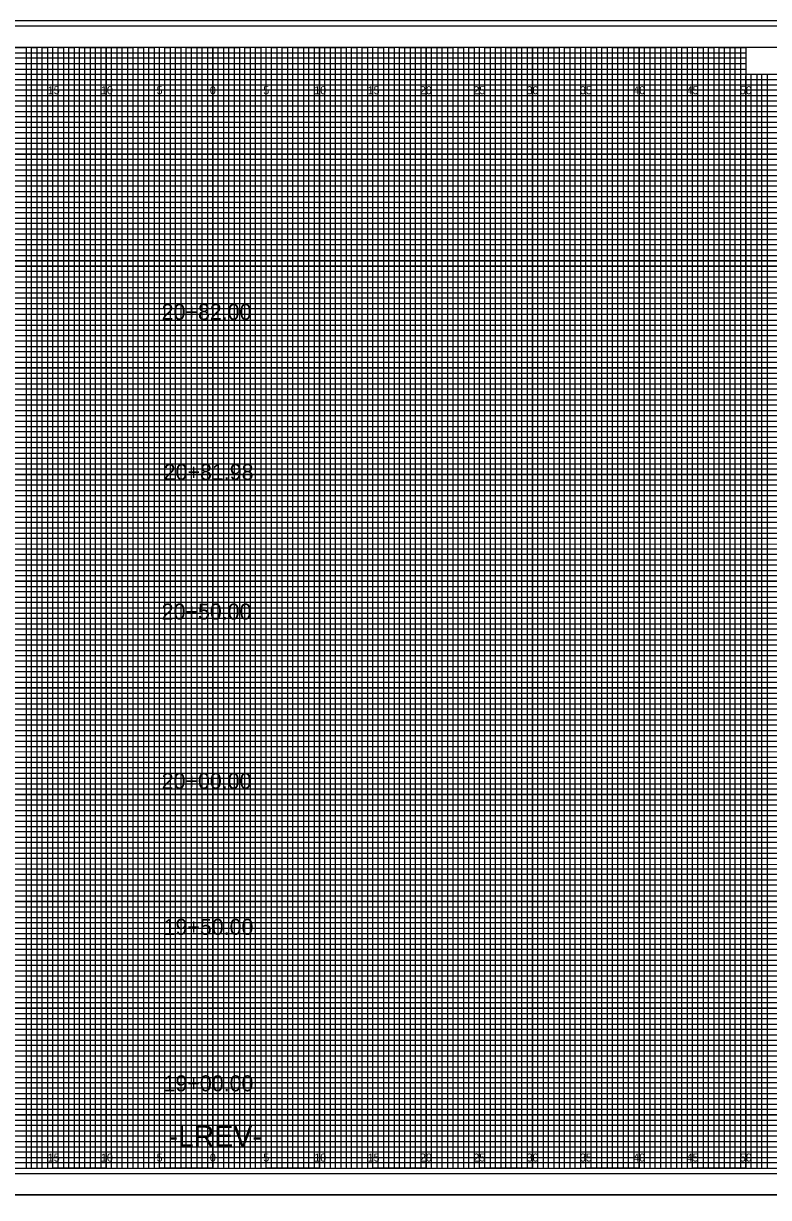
# Model space of a CAD drawing. Extents: x -8 to 533, y -20 to 768.
# Drawn here: x 62.2 to 132.1, y 217.2 to 327.2 of the extents above; entities that cross this region are included whole.
import ezdxf

# ---------------------------------------------------------------- set-up
doc = ezdxf.new("R2010")
doc.units = 0
for name, color, linetype in [('Prop XS Alignment Label', 7, 'Continuous'), ('Prop XS Offset Labels', 7, 'Continuous'), ('Prop XS Station Labels', 7, 'Continuous'), ('Sheet Cross Section CELL', 7, 'Continuous'), ('Sheet Cross Section Grid Major CELL', 7, 'Continuous'), ('Sheet Cross Section Grid Middle CELL', 7, 'Continuous'), ('Sheet Cross Section Grid Minor 1 CELL', 7, 'Continuous'), ('Sheet Cross Section Grid Minor 2 CELL', 7, 'Continuous'), ('Sheet Cutting Line CELL', 7, 'Continuous'), ('Sheet DOT Grid CELL', 7, 'Continuous'), ('Sheet Plot Border Inside CELL', 7, 'Continuous'), ('Sheet Plot Border Outside CELL', 7, 'Continuous'), ('WEI Plot Border', 7, 'Continuous')]:
    doc.layers.add(name, color=color, linetype=linetype)

msp = doc.modelspace()

# ---------------------------------------------------------------- linework, layer by layer
at = {"layer": 'Sheet Cross Section CELL'}
for points in [[(160, 325), (0, 325), (0, 220), (160, 220)], [(140, 325), (130, 325), (130, 322.51), (140, 322.51)]]:
    msp.add_lwpolyline(points, close=True, dxfattribs=at)
at = {"layer": 'Sheet Cross Section Grid Major CELL'}
for p, q in [((65, 325), (60, 325)), ((65, 220), (65, 325)), ((75, 325), (70, 325)), ((70, 325), (70, 220)), ((75, 220), (75, 325)), ((85, 325), (80, 325)), ((80, 325), (80, 220)), ((85, 220), (85, 325)), ((95, 325), (90, 325)), ((90, 325), (90, 220)), ((95, 220), (95, 325)), ((105, 325), (100, 325)), ((100, 325), (100, 220)), ((105, 220), (105, 325)), ((115, 325), (110, 325)), ((110, 325), (110, 220)), ((115, 220), (115, 325)), ((125, 325), (120, 325)), ((120, 325), (120, 220)), ((125, 220), (125, 325)), ((130, 325), (130, 220)), ((70, 220), (65, 220)), ((80, 220), (75, 220)), ((90, 220), (85, 220)), ((100, 220), (95, 220)), ((110, 220), (105, 220)), ((120, 220), (115, 220)), ((130, 220), (125, 220))]:
    msp.add_line(p, q, dxfattribs=at)
for points in [[(0, 320), (160, 320), (160, 315), (0, 315)], [(0, 310), (160, 310), (160, 305), (0, 305)], [(0, 300), (160, 300), (160, 295), (0, 295)], [(0, 290), (160, 290), (160, 285), (0, 285)], [(0, 280), (160, 280), (160, 275), (0, 275)], [(0, 270), (160, 270), (160, 265), (0, 265)], [(0, 260), (160, 260), (160, 255), (0, 255)], [(0, 250), (160, 250), (160, 245), (0, 245)], [(0, 240), (160, 240), (160, 235), (0, 235)], [(0, 230), (160, 230), (160, 225), (0, 225)]]:
    msp.add_lwpolyline(points, dxfattribs=at)
at = {"layer": 'Sheet Cross Section Grid Middle CELL'}
for points in [[(57.5, 325), (62.5, 325), (62.5, 220), (67.5, 220), (67.5, 325), (72.5, 325), (72.5, 220), (77.5, 220), (77.5, 325), (82.5, 325), (82.5, 220), (87.5, 220), (87.5, 325), (92.5, 325), (92.5, 220), (97.5, 220), (97.5, 325), (102.5, 325), (102.5, 220), (107.5, 220), (107.5, 325), (112.5, 325), (112.5, 220), (117.5, 220), (117.5, 325), (122.5, 325), (122.5, 220), (127.5, 220), (127.5, 325), (129.97, 325), (130, 325), (130, 322.5), (132.5, 322.5)], [(0, 322.5), (137.5, 322.5)], [(0, 312.5), (160, 312.5), (160, 317.5), (0, 317.5)], [(0, 302.5), (160, 302.5), (160, 307.5), (0, 307.5)], [(0, 292.5), (160, 292.5), (160, 297.5), (0, 297.5)], [(0, 282.5), (160, 282.5), (160, 287.5), (0, 287.5)], [(0, 272.5), (160, 272.5), (160, 277.5), (0, 277.5)], [(0, 262.5), (160, 262.5), (160, 267.5), (0, 267.5)], [(0, 252.5), (160, 252.5), (160, 257.5), (0, 257.5)], [(0, 242.5), (160, 242.5), (160, 247.5), (0, 247.5)], [(0, 232.5), (160, 232.5), (160, 237.5), (0, 237.5)], [(0, 222.5), (160, 222.5), (160, 227.5), (0, 227.5)]]:
    msp.add_lwpolyline(points, dxfattribs=at)
at = {"layer": 'Sheet Cross Section Grid Minor 1 CELL'}
for p, q in [((0, 324.5), (130, 324.5)), ((130, 324.5), (130, 323.99)), ((130, 323.99), (0, 323.99)), ((0, 323.5), (130, 323.5)), ((130, 323.5), (130, 322.94)), ((130, 322.94), (0, 322.94)), ((0, 322), (160, 322))]:
    msp.add_line(p, q, dxfattribs=at)
for points in [[(0, 321.5), (135, 321.5), (160, 321.5), (160, 321), (0, 321)], [(0, 320.5), (160, 320.5), (160, 319.5), (0, 319.5)], [(0, 319), (160, 319), (160, 318.5), (0, 318.49)], [(0, 318), (160, 318), (160, 317), (0, 317)], [(0, 316.5), (160, 316.5), (160, 316), (0, 316)], [(0, 315.5), (160, 315.5), (160, 314.5), (0, 314.5)], [(0, 314), (160, 314), (160, 313.5), (0, 313.5)], [(0, 313), (160, 313), (160, 312), (0, 312)], [(0, 311.5), (160, 311.5), (160, 311), (0, 311)], [(0, 310.5), (160, 310.5), (160, 309.5), (0, 309.5)], [(0, 309), (160, 309), (160, 308.5), (0, 308.5)], [(0, 308), (160, 308), (160, 306.98), (160, 306.5), (160, 306), (0, 306)], [(0, 307), (160, 307), (160, 306.5), (0, 306.5)], [(0, 305.5), (160, 305.5), (160, 304.5), (0, 304.51)], [(0, 304.51), (160, 304.5), (160, 304), (0, 304)], [(0, 303.5), (160, 303.5), (160, 303), (0, 303)], [(0, 302), (160, 302), (160, 301.5), (0, 301.5)], [(0, 301), (160, 301), (160, 300.5), (0, 300.5)], [(-0.04, 299.44), (160, 299.44), (160, 298.94), (-0.04, 298.94)], [(0, 298.5), (160, 298.5), (160, 298), (0, 298)], [(0, 297), (160, 297), (160, 296.5), (0, 296.5)], [(0, 296), (160, 296), (160, 295.5), (0, 295.5)], [(0, 294.5), (160, 294.5), (160, 294), (0, 294)], [(0, 293.5), (160, 293.5), (160, 293), (0, 293)], [(0, 292), (160, 292), (160, 291.5), (0, 291.5)], [(0, 291), (160, 291), (160, 290.5), (0, 290.5)], [(0, 289.5), (160, 289.5), (160, 288.99), (0, 289)], [(0, 288.5), (160, 288.5), (160, 288), (0, 288)], [(0, 287), (160, 287), (160, 286.5), (0, 286.5)], [(0, 286), (160, 286), (160, 285.5), (0, 285.5)], [(0, 284.5), (160, 284.5), (160, 284), (0, 284)], [(0, 283.5), (160, 283.5), (160, 283), (0, 283)], [(0, 282), (160, 282), (160, 281.5), (0, 281.5)], [(0, 281), (160, 281), (160, 280.5), (0, 280.5)], [(0, 279.5), (160, 279.5), (160, 279), (0, 279)], [(0, 278.5), (160.03, 278.45), (160, 278), (0, 278)], [(0, 277), (160, 277), (160, 276.5), (0, 276.5)], [(0, 276), (160, 276), (160, 275.5), (0, 275.5)], [(0, 274.5), (160, 274.5), (160, 274), (0, 274)], [(0, 273.5), (160, 273.5), (160, 273), (0, 273)], [(0, 272), (160, 272), (160, 271.5), (0, 271.5)], [(0, 271), (160, 271), (160, 270.5), (0, 270.5)], [(0, 269.5), (160, 269.5), (160, 269), (0, 269)], [(0, 268.5), (160, 268.5), (160, 268), (0, 268)], [(0, 267), (160, 267), (160, 266.5), (0, 266.5)], [(0, 266), (160, 266), (160, 265.5), (0, 265.5)], [(0, 264.5), (160, 264.5), (160, 264), (0, 264)], [(0, 263.5), (160, 263.5), (160, 263), (0, 263)], [(0, 262), (160, 262), (160, 261.5), (0, 261.5)], [(0, 261), (160, 261), (160, 260.5), (0, 260.5)], [(0, 259.5), (160, 259.5), (160, 258.99), (0, 259)], [(0, 258.5), (160, 258.5), (160, 258), (0, 258)], [(0, 257), (160, 257), (160, 256.5), (0, 256.5)], [(0, 256), (160, 256), (160, 255.5), (0, 255.5)], [(0, 254.5), (160, 254.5), (160, 254), (0, 254)], [(0, 253.5), (160, 253.5), (160, 253), (0, 253)], [(0, 252), (160, 252), (160, 251.5), (0, 251.5)], [(0, 251), (160, 251), (160, 250.5), (0, 250.5)], [(0, 249.5), (160, 249.5), (160, 249), (0, 249)], [(0, 248.5), (160.03, 248.46), (160, 248), (0, 248)], [(0, 247), (160, 247), (160, 246.5), (0, 246.5)], [(0, 246), (160, 246), (160, 245.5), (0, 245.5)], [(0, 244.5), (160, 244.5), (160, 244), (0, 244)], [(0, 243.5), (160, 243.5), (160, 243), (0, 243)], [(0, 242), (160, 242), (160, 241.5), (0, 241.5)], [(0, 241), (160, 241), (160, 240.5), (0, 240.5)], [(0, 239.5), (160, 239.5), (160, 239), (0, 239)], [(0, 238.5), (160, 238.5), (160, 238), (0, 238)], [(0, 237), (160, 237), (160, 236.5), (0, 236.5)], [(0, 236), (160, 236), (160, 235.5), (0, 235.5)], [(0, 234.5), (160, 234.5), (160, 234), (0, 234)], [(0, 233.5), (160, 233.5), (160, 233), (0, 233)], [(0, 232), (160, 232), (160, 231.5), (0, 231.5)], [(0, 231), (160, 231), (160, 230.5), (0, 230.5)], [(0, 229.5), (160, 229.5), (160, 229), (0, 229)], [(0, 228.5), (160, 228.5), (160, 228), (0, 228)], [(0, 227), (160, 227), (160, 226.5), (0, 226.5)], [(0, 226), (160, 226), (160, 225.5), (0, 225.5)], [(0, 224.5), (160, 224.5), (160, 224), (0, 224)], [(0, 223.5), (160, 223.5), (160, 223), (0, 223)], [(0, 222), (160, 222), (160, 221.5), (0, 221.5)], [(0, 221), (160, 221), (160, 220.5), (0, 220.5)]]:
    msp.add_lwpolyline(points, dxfattribs=at)
at = {"layer": 'Sheet Cross Section Grid Minor 2 CELL'}
for points in [[(62.5, 220), (63, 220), (63, 325), (63.5, 325), (63.5, 220)], [(63.5, 220), (64, 220), (64, 325), (64.5, 325), (64.5, 220)], [(65, 220), (65.5, 220), (65.5, 325), (66, 325), (66, 220)], [(66, 220), (66.5, 220), (66.5, 325), (67, 325), (67, 220)], [(67.5, 220), (68, 220), (68, 325), (68.5, 325), (68.5, 220)], [(68.5, 220), (69, 220), (69, 325), (69.5, 325), (69.5, 220)], [(70, 220), (70.5, 220), (70.5, 325), (71, 325), (71, 220)], [(71, 220), (71.5, 220), (71.5, 325), (72, 325), (72, 220)], [(72.5, 220), (73, 220), (73, 325), (73.5, 325), (73.5, 220)], [(73.5, 220), (74, 220), (74, 325), (74.5, 325), (74.5, 220)], [(75, 220), (75.5, 220), (75.5, 325), (76, 325), (76, 220)], [(76, 220), (76.5, 220), (76.5, 325), (77, 325), (77, 220)], [(77.5, 220), (78, 220), (78, 325), (78.5, 325), (78.5, 220)], [(78.5, 220), (79, 220), (79, 325), (79.5, 325), (79.5, 220)], [(80, 220), (80.5, 220), (80.5, 325), (81, 325), (81, 220)], [(81, 220), (81.5, 220), (81.5, 325), (82, 325), (82, 220)], [(82.5, 220), (83, 220), (83, 325), (83.5, 325), (83.5, 220)], [(83.5, 220), (84, 220), (84, 325), (84.5, 325), (84.5, 220)], [(85, 220), (85.5, 220), (85.5, 325), (86, 325), (86, 220)], [(86, 220), (86.5, 220), (86.5, 325), (87, 325), (87, 220)], [(87.5, 220), (88, 220), (88, 325), (88.5, 325), (88.5, 220)], [(88.5, 220), (89, 220), (89, 325), (89.5, 325), (89.5, 220)], [(90, 220), (90.5, 220), (90.5, 325), (91, 325), (91, 220)], [(91, 220), (91.5, 220), (91.5, 325), (92, 325), (92, 220)], [(92.5, 220), (93, 220), (93, 325), (93.5, 325), (93.5, 220)], [(93.5, 220), (94, 220), (94, 325), (94.5, 325), (94.5, 220)], [(95, 220), (95.5, 220), (95.5, 325), (96, 325), (96, 220)], [(96, 220), (96.5, 220), (96.5, 325), (97, 325), (97, 220)], [(97.5, 220), (98, 220), (98, 325), (98.5, 325), (98.5, 220)], [(98.5, 220), (99, 220), (99, 325), (99.5, 325), (99.5, 220)], [(100, 220), (100.5, 220), (100.5, 325), (101, 325), (101, 220)], [(101, 220), (101.5, 220), (101.5, 325), (102, 325), (102, 220)], [(102.5, 220), (103, 220), (103, 325), (103.5, 325), (103.5, 220)], [(103.5, 220), (104, 220), (104, 325), (104.5, 325), (104.5, 220)], [(105, 220), (105.5, 220), (105.5, 325), (106, 325), (106, 220)], [(106, 220), (106.5, 220), (106.5, 325), (107, 325), (107, 220)], [(107.5, 220), (108, 220), (108, 325), (108.5, 325), (108.5, 220)], [(108.5, 220), (109, 220), (109, 325), (109.5, 325), (109.5, 220)], [(110, 220), (110.5, 220), (110.5, 325), (111, 325), (111, 220)], [(111, 220), (111.5, 220), (111.5, 325), (112, 325), (112, 220)], [(112.5, 220), (113, 220), (113, 325), (113.5, 325), (113.5, 220)], [(113.5, 220), (114, 220), (114, 325), (114.5, 325), (114.5, 220)], [(115, 220), (115.5, 220), (115.5, 325), (116, 325), (116, 220)], [(116, 220), (116.5, 220), (116.5, 325), (117, 325), (117, 220)], [(117.5, 220), (118, 220), (118, 325), (118.5, 325), (118.5, 220)], [(118.5, 220), (119, 220), (119, 325), (119.5, 325), (119.5, 220)], [(120, 220), (120.5, 220), (120.5, 325), (121, 325), (121, 220)], [(121, 220), (121.5, 220), (121.5, 325), (122, 325), (122, 220)], [(122.5, 220), (123, 220), (123, 325), (123.5, 325), (123.5, 220)], [(123.5, 220), (124, 220), (124, 325), (124.5, 325), (124.5, 220)], [(125, 220), (125.5, 220), (125.5, 325), (126, 325), (126, 220)], [(126, 220), (126.5, 220), (126.5, 325), (127, 325), (127, 220)], [(127.5, 220), (128, 220), (128, 325), (128.5, 325), (128.5, 220)], [(128.5, 220), (129, 220), (129, 325), (129.5, 325), (129.5, 220)], [(130, 220), (130.5, 220), (130.5, 322.5), (131.01, 322.5), (131.01, 220)], [(131, 220), (131.5, 220), (131.5, 322.5), (132, 322.5), (132, 220)]]:
    msp.add_lwpolyline(points, dxfattribs=at)
at = {"layer": 'Sheet Cutting Line CELL'}
for p, q in [((161.65, 327), (-6.7, 327)), ((-6.7, 217.5), (161.65, 217.5))]:
    msp.add_line(p, q, dxfattribs=at)
at = {"layer": 'Sheet DOT Grid CELL'}
for p, q in [((65, 220), (65, 325)), ((70, 220), (70, 325)), ((75, 220), (75, 325)), ((80, 220), (80, 325)), ((85, 220), (85, 325)), ((90, 220), (90, 325)), ((95, 220), (95, 325)), ((100, 220), (100, 325)), ((105, 220), (105, 325)), ((110, 220), (110, 325)), ((115, 220), (115, 325)), ((120, 220), (120, 325)), ((125, 220), (125, 325)), ((130, 220), (130, 322.34)), ((0, 320), (160, 320)), ((0, 315), (160, 315)), ((0, 310), (160, 310)), ((0, 305), (160, 305)), ((0, 300), (160, 300)), ((0, 295), (160, 295)), ((0, 290), (160, 290)), ((0, 285), (160, 285)), ((0, 280), (160, 280)), ((0, 275), (160, 275)), ((0, 270), (160, 270)), ((0, 265), (160, 265)), ((0, 260), (160, 260)), ((0, 255), (160, 255)), ((0, 250), (160, 250)), ((0, 245), (160, 245)), ((0, 240), (160, 240)), ((0, 235), (160, 235)), ((0, 230), (160, 230)), ((0, 225), (160, 225))]:
    msp.add_line(p, q, dxfattribs=at)
at = {"layer": 'Sheet Plot Border Inside CELL'}
msp.add_lwpolyline([(-5.4, 219.5), (161.2, 219.5), (161.2, 325), (-5.4, 325)], close=True, dxfattribs=at)
at = {"layer": 'Sheet Plot Border Outside CELL'}
msp.add_lwpolyline([(-6.7, 217.5), (161.65, 217.5), (161.65, 327), (-6.7, 327)], close=True, dxfattribs=at)
at = {"layer": 'WEI Plot Border'}
for points in [[(-7.5, 217.5), (162.5, 217.5), (162.5, 327.5), (-7.5, 327.5)], [(-7.5, 107.5), (162.5, 107.5), (162.5, 217.5), (-7.5, 217.5)]]:
    msp.add_lwpolyline(points, close=True, dxfattribs=at)

# ---------------------------------------------------------------- texts
at = {"layer": 'Prop XS Alignment Label'}
msp.add_text('-LREV-', height=2, dxfattribs=at).set_placement((75.84, 222))
at = {"layer": 'Prop XS Offset Labels'}
for s, p in [('15', (64.53, 320.62)), ('10', (69.52, 320.62)), ('5', (74.74, 320.62)), ('0', (79.73, 320.62)), ('0', (79.73, 320.62)), ('5', (84.74, 320.62)), ('10', (89.52, 320.62)), ('15', (94.53, 320.62)), ('20', (99.43, 320.62)), ('25', (104.44, 320.62)), ('30', (109.43, 320.62)), ('35', (114.44, 320.62)), ('40', (119.43, 320.62)), ('45', (124.44, 320.62)), ('50', (129.43, 320.62)), ('15', (64.53, 220.62)), ('10', (69.52, 220.62)), ('5', (74.74, 220.62)), ('0', (79.73, 220.62)), ('0', (79.73, 220.62)), ('5', (84.74, 220.62)), ('10', (89.52, 220.62)), ('15', (94.53, 220.62)), ('20', (99.43, 220.62)), ('25', (104.44, 220.62)), ('30', (109.43, 220.62)), ('35', (114.44, 220.62)), ('40', (119.43, 220.62)), ('45', (124.44, 220.62)), ('50', (129.43, 220.62))]:
    msp.add_text(s, height=0.75, dxfattribs=at).set_placement(p)
at = {"layer": 'Prop XS Station Labels'}
for s, p in [('20+82.00', (75.21, 299.48)), ('20+81.98', (75.4, 284.48)), ('20+50.00', (75.21, 271.4)), ('20+00.00', (75.21, 255.53)), ('19+50.00', (75.39, 241.86)), ('19+00.00', (75.39, 227.2))]:
    msp.add_text(s, height=1.5, dxfattribs=at).set_placement(p)

doc.saveas('drawing.dxf')
